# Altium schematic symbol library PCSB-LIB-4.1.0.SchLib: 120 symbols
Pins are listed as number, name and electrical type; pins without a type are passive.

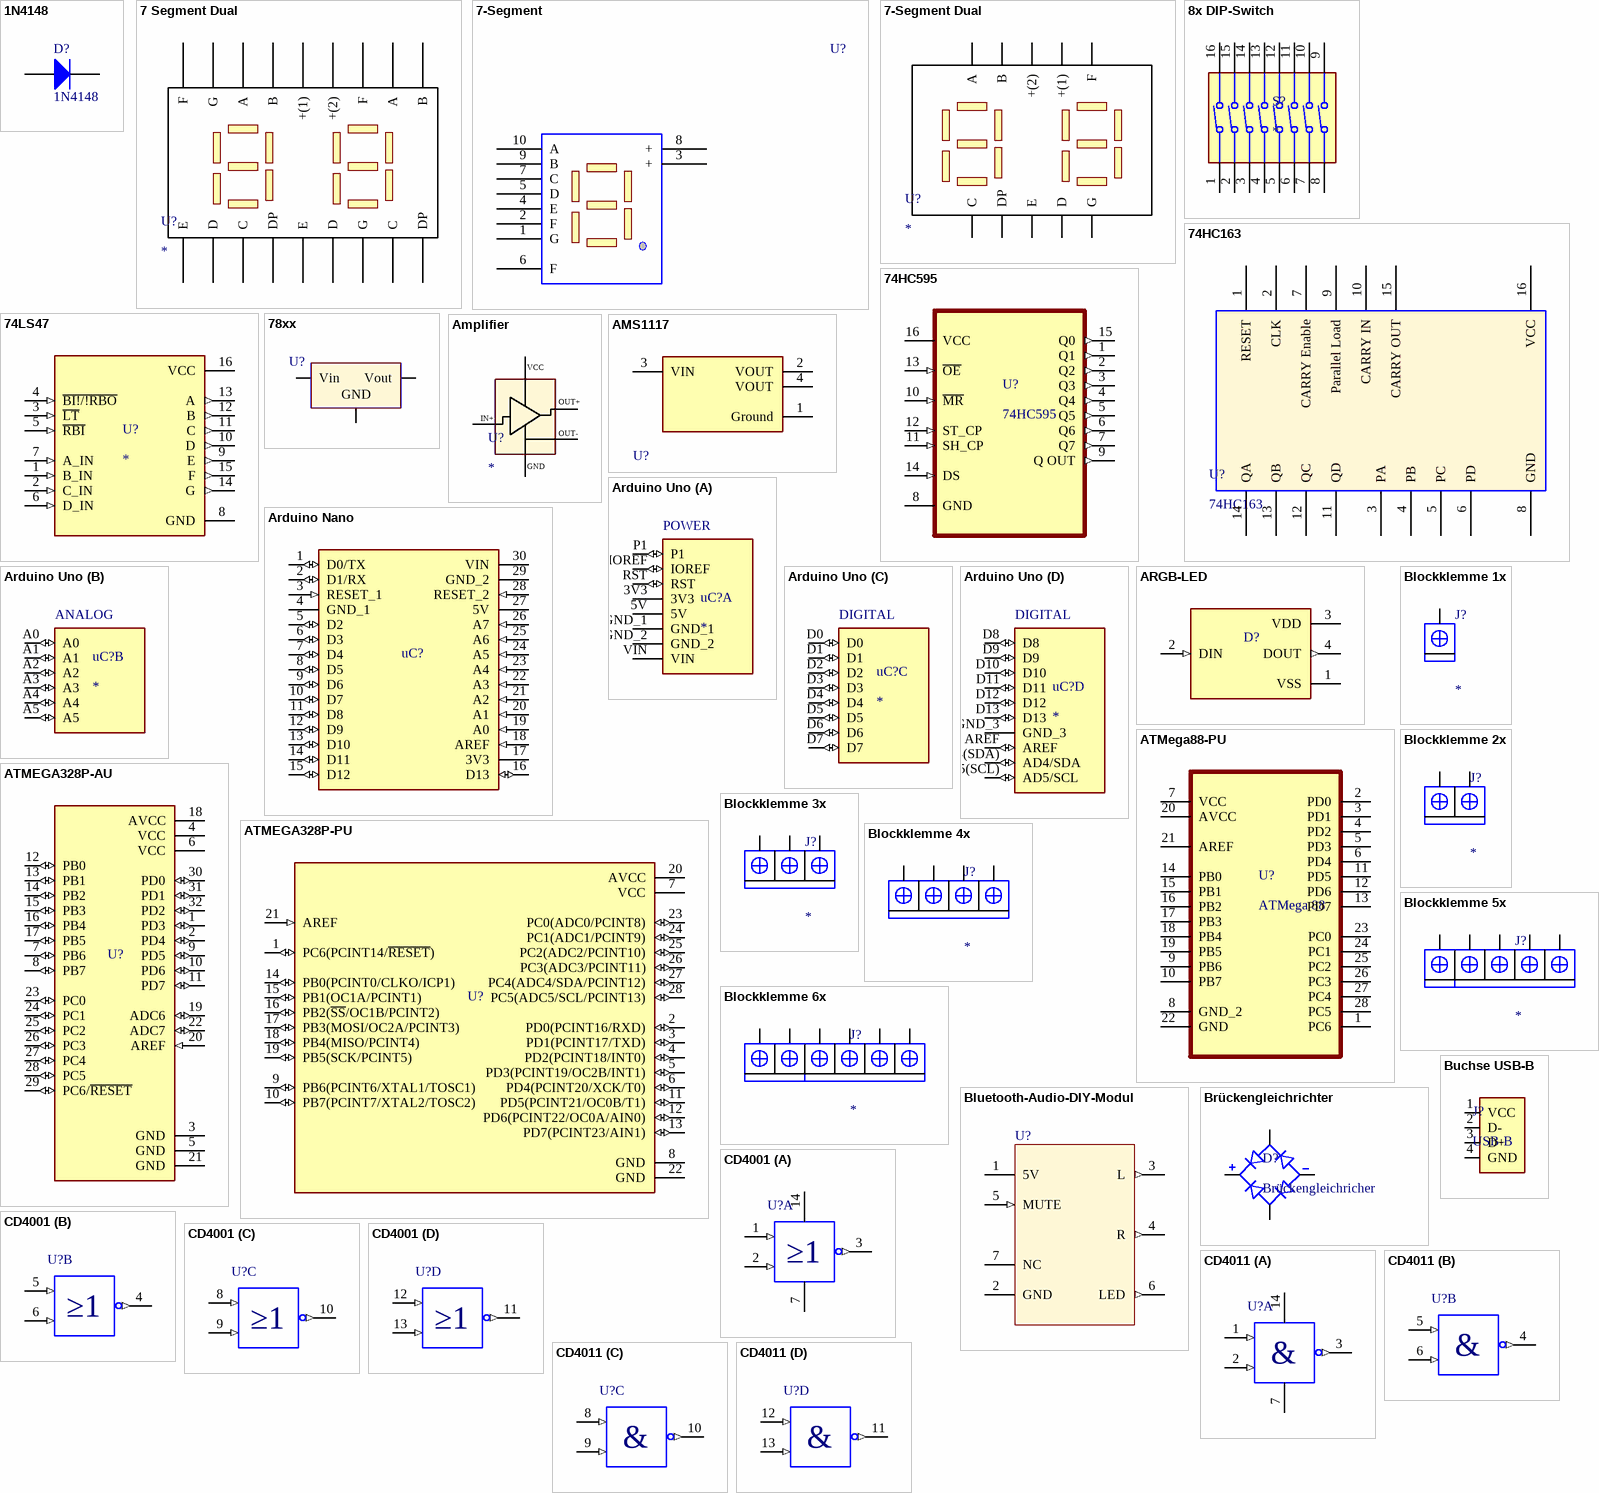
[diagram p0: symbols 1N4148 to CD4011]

## 1N4148
designator D?
Diode
footprint DIODE-0.4
pins: 1 A, 2 K

## 7 Segment Dual
designator U?
footprint 7 Segment Dual Klein
footprint 7 Segment Dual Groß
pins: 1 E, 2 D, 3 C, 4 DP, 5 E, 6 D, 7 G, 8 C, 9 DP, 10 B, 11 A, 12 F, 13 +(2), 14 +(1), 15 B, 16 A, 17 G, 18 F

## 7-Segment
designator U?  (value not drawn)
7-Segment Display
footprint 7-Segment
pins: 1 G, 2 F, 3 +, 4 E, 5 D, 6 F, 7 C, 8 +, 9 B, 10 A

## 7-Segment Dual
designator U?
footprint 7 Seg Einfach
pins: 1 C, 2 DP, 3 E, 4 D, 5 G, 6 F, 7 +(1), 8 +(2), 9 B, 10 A

## 8x DIP-Switch
designator S?
MP: 418117170908; MF: WÃ¼rth Elektronik
footprint DIP 2x8
pins: 1, 2, 3, 4, 5, 6, 7, 8, 9, 10, 11, 12, 13, 14, 15, 16

## 74HC163
designator U?
Counter-IC; Mfr_Name: Texas Instruments
footprint DIP-16
pins: 1 RESET, 2 CLK, 3 PA, 4 PB, 5 PC, 6 PD, 7 CARRY Enable, 8 GND, 9 Parallel Load, 10 CARRY IN, 11 QD, 12 QC, 13 QB, 14 QA, 15 CARRY OUT, 16 VCC

## 74HC595
designator U?
Schieberegister; MP: 74HC595PW/AUJ; MF: NXP Semiconductors
footprint SOP-16
footprint DIP-16
footprint SO-16
pins: 1 Q1 (out), 2 Q2 (out), 3 Q3 (out), 4 Q4 (out), 5 Q5 (out), 6 Q6 (out), 7 Q7 (out), 8 GND, 9 Q OUT (out), 10 ~{MR} (in), 11 SH_CP (in), 12 ST_CP (in), 13 ~{OE} (in), 14 DS (in), 15 Q0 (out), 16 VCC (power)

## 74LS47
designator U?
BCD-to-Seven-Segment Decoders/Drivers 16-PDIP 0 to 70; MP: SN74LS47N; MF: Texas Instruments
footprint DIP-16
footprint SO-16
pins: 1 B_IN (in), 2 C_IN (in), 3 ~{LT} (in), 4 ~{BI!/!RBO} (in), 5 ~{RBI} (in), 6 D_IN (in), 7 A_IN (in), 8 GND (power), 9 E (out), 10 D (out), 11 C (out), 12 B (out), 13 A (out), 14 G (out), 15 F (out), 16 VCC (power)

## 78xx
designator U?  (value not drawn)
Spannungswander
footprint TO-92/BCE
footprint TO-220H
footprint TO-220V
pins: 1 Vin, 2 Vout, 3 GND

## Amplifier
designator U?
footprint Verstärker 5V
pins: 0, 1, 2, 3, 4

## AMS1117
designator U?
Spannungswandler; Manufacturer Part Number: AMS1117-3.3; Manufacturer: Advanced Monolithic Systems; Dropout Voltage: 1.1V; Output Type: Fixed; Nominal Supply Current: 5mA; Output Current: 1A; Output Voltage: 3.3V; Max Power Dissipation: 1.2W; Max Supply Voltage: 15V; Number Of Outputs: 1; Standoff Height: 0.64mm; Max Junction Temp: +125°C
footprint AMS1117_1
footprint AMS1117_2
footprint AMS1117_3
pins: 1 Ground (power), 2 VOUT, 3 VIN (power), 4 VOUT

## Arduino Nano
designator uC?  (value not drawn)
Microcontroller; MP: A000005
footprint Arduino-Nano
pins: 1 D0/TX (io), 2 D1/RX (io), 3 RESET_1 (in), 4 GND_1 (power), 5 D2 (io), 6 D3 (io), 7 D4 (io), 8 D5 (io), 9 D6 (io), 10 D7 (io), 11 D8 (io), 12 D9 (io), 13 D10 (io), 14 D11 (io), 15 D12 (io), 16 D13 (io), 17 3V3 (power), 18 AREF (in), 19 A0 (in), 20 A1 (in), 21 A2 (in), 22 A3 (in), 23 A4 (in), 24 A5 (in), 25 A6 (in), 26 A7 (in), 27 5V (power), 28 RESET_2 (in), 29 GND_2 (power), 30 VIN (power)

## Arduino Uno
designator uC?
MP: A000066; MF: Arduino
footprint Arduino Uno
part A pins: 3V3 (power), 5V (power), GND_1 (power), GND_2 (power), IOREF (io), P1 (io), RST (io), VIN (power)
part B pins: A0 (io), A1 (io), A2 (io), A3 (io), A4 (io), A5 (io)
part C pins: D0 (io), D1 (io), D2 (io), D3 (io), D4 (io), D5 (io), D6 (io), D7 (io)
part D pins: A4(SDA) AD4/SDA (io), A5(SCL) AD5/SCL (io), AREF (io), D8 (io), D9 (io), D10 (io), D11 (io), D12 (io), D13 (io), GND_3 (power)

## ARGB-LED
designator D?  (value not drawn)
Addressable LED; MP: 1655
footprint LED_ARGB
pins: 1 VSS (power), 2 DIN (in), 3 VDD (power), 4 DOUT (out)

## ATMega88-PU
designator U?, comment ATMega 88
8-bit Microcontroller with In-System Programmable Flash; MP: ATMEGA88-20PU
footprint DIP-28
pins: 1 PC6, 2 PD0, 3 PD1, 4 PD2, 5 PD3, 6 PD4, 7 VCC, 8 GND_2, 9 PB6, 10 PB7, 11 PD5, 12 PD6, 13 PD7, 14 PB0, 15 PB1, 16 PB2, 17 PB3, 18 PB4, 19 PB5, 20 AVCC, 21 AREF, 22 GND, 23 PC0, 24 PC1, 25 PC2, 26 PC3, 27 PC4, 28 PC5

## ATMEGA328P-AU
designator U?, comment ATMega 328(p)  (value not drawn)
MF: Microchip Technology; MP: ATMEGA328P-AU
footprint ATMEGA328P
pins: 1 PD3 (io), 2 PD4 (io), 3 GND (power), 4 VCC (power), 5 GND (power), 6 VCC (power), 7 PB6 (io), 8 PB7 (io), 9 PD5 (io), 10 PD6 (io), 11 PD7 (io), 12 PB0 (io), 13 PB1 (io), 14 PB2 (io), 15 PB3 (io), 16 PB4 (io), 17 PB5 (io), 18 AVCC (power), 19 ADC6 (io), 20 AREF (in), 21 GND (power), 22 ADC7 (io), 23 PC0 (io), 24 PC1 (io), 25 PC2 (io), 26 PC3 (io), 27 PC4 (io), 28 PC5 (io), 29 PC6/~{RESET} (io), 30 PD0 (io), 31 PD1 (io), 32 PD2 (io)

## ATMEGA328P-PU
designator U?  (value not drawn)
Microcontroller; MF: Microchip Technology; MP: ATMEGA328-PU
footprint DIP-28
pins: 1 PC6(PCINT14/~{RESET}) (io), 2 PD0(PCINT16/RXD) (io), 3 PD1(PCINT17/TXD) (io), 4 PD2(PCINT18/INT0) (io), 5 PD3(PCINT19/OC2B/INT1) (io), 6 PD4(PCINT20/XCK/T0) (io), 7 VCC (power), 8 GND (power), 9 PB6(PCINT6/XTAL1/TOSC1) (io), 10 PB7(PCINT7/XTAL2/TOSC2) (io), 11 PD5(PCINT21/OC0B/T1) (io), 12 PD6(PCINT22/OC0A/AIN0) (io), 13 PD7(PCINT23/AIN1) (io), 14 PB0(PCINT0/CLKO/ICP1) (io), 15 PB1(OC1A/PCINT1) (io), 16 PB2(~{SS}/OC1B/PCINT2) (io), 17 PB3(MOSI/OC2A/PCINT3) (io), 18 PB4(MISO/PCINT4) (io), 19 PB5(SCK/PCINT5) (io), 20 AVCC (power), 21 AREF (in), 22 GND (power), 23 PC0(ADC0/PCINT8) (io), 24 PC1(ADC1/PCINT9) (io), 25 PC2(ADC2/PCINT10) (io), 26 PC3(ADC3/PCINT11) (io), 27 PC4(ADC4/SDA/PCINT12) (io), 28 PC5(ADC5/SCL/PCINT13) (io)

## Blockklemme 1x
designator J?
Stecker
footprint Blockklemme 1x
pins: 1

## Blockklemme 2x
designator J?
Stecker
footprint Blockklemme 2x
pins: 1, 2

## Blockklemme 3x
designator J?
Stecker
footprint Blockklemme 3x
pins: 1, 2, 3 2

## Blockklemme 4x
designator J?
Stecker
footprint Blockklemme 4x
pins: 1, 2, 3 2, 4 2

## Blockklemme 5x
designator J?
Stecker
footprint Blockklemme 5x
pins: 1, 2, 3 2, 4 2, 5 2

## Blockklemme 6x
designator J?
Stecker
footprint Blockklemme 6x
pins: 1, 2, 3 2, 4 2, 5 2, 6 2

## Bluetooth-Audio-DIY-Modul
designator U?  (value not drawn)
Bluetooth Modul
footprint Bluetooth Audio SIP7
pins: 1 5V (power), 2 GND (power), 3 L (out), 4 R (out), 5 MUTE (in), 6 LED (out), 7 NC

## Brückengleichrichter
designator D?, comment Brückengleichricher
MF: NTE Electronics, Inc; MP: NTE53010
footprint FBR_Big
footprint FBR-little
pins: 1 POS, 2 AC1, 3 AC2, 4 NEG

## Buchse USB-B
designator J?, comment USB-B
MF: On Shore; MP: USB-B1HSB6
footprint USB-B
pins: 1 VCC (power), 2 D- (io), 3 D+ (io), 4 GND (power)

## CD4001
designator U?  (value not drawn)
NOR Gatter; PartNumber: LM358AN; Manufacturer: National Semiconductor; PackageTopMarking: NSUZXYTTE#*LM*358AN; PowerWise: N; CompType: Amplifiers
footprint DIP-14
footprint SO-14
part A pins: 1 A (in), 2 B (in), 3 OUTAB (out), 7 GND (power), 14 V+ (power)
part B pins: 4 OUTCD (out), 5 C (in), 6 D (in)
part C pins: 8 E (in), 9 F (in), 10 OUTEF (out)
part D pins: 11 OUTGH (out), 12 G (in), 13 H (in)

## CD4011
designator U?  (value not drawn)
NAND Gatter; PartNumber: LM358AN; Manufacturer: National Semiconductor; PackageTopMarking: NSUZXYTTE#*LM*358AN; PowerWise: N; CompType: Amplifiers
footprint DIP-14
footprint SO-14
part A pins: 1 A (in), 2 B (in), 3 OUTAB (out), 7 GND (power), 14 V+ (power)
part B pins: 4 OUTCD (out), 5 C (in), 6 D (in)
part C pins: 8 E (in), 9 F (in), 10 OUTEF (out)
part D pins: 11 OUTGH (out), 12 G (in), 13 H (in)

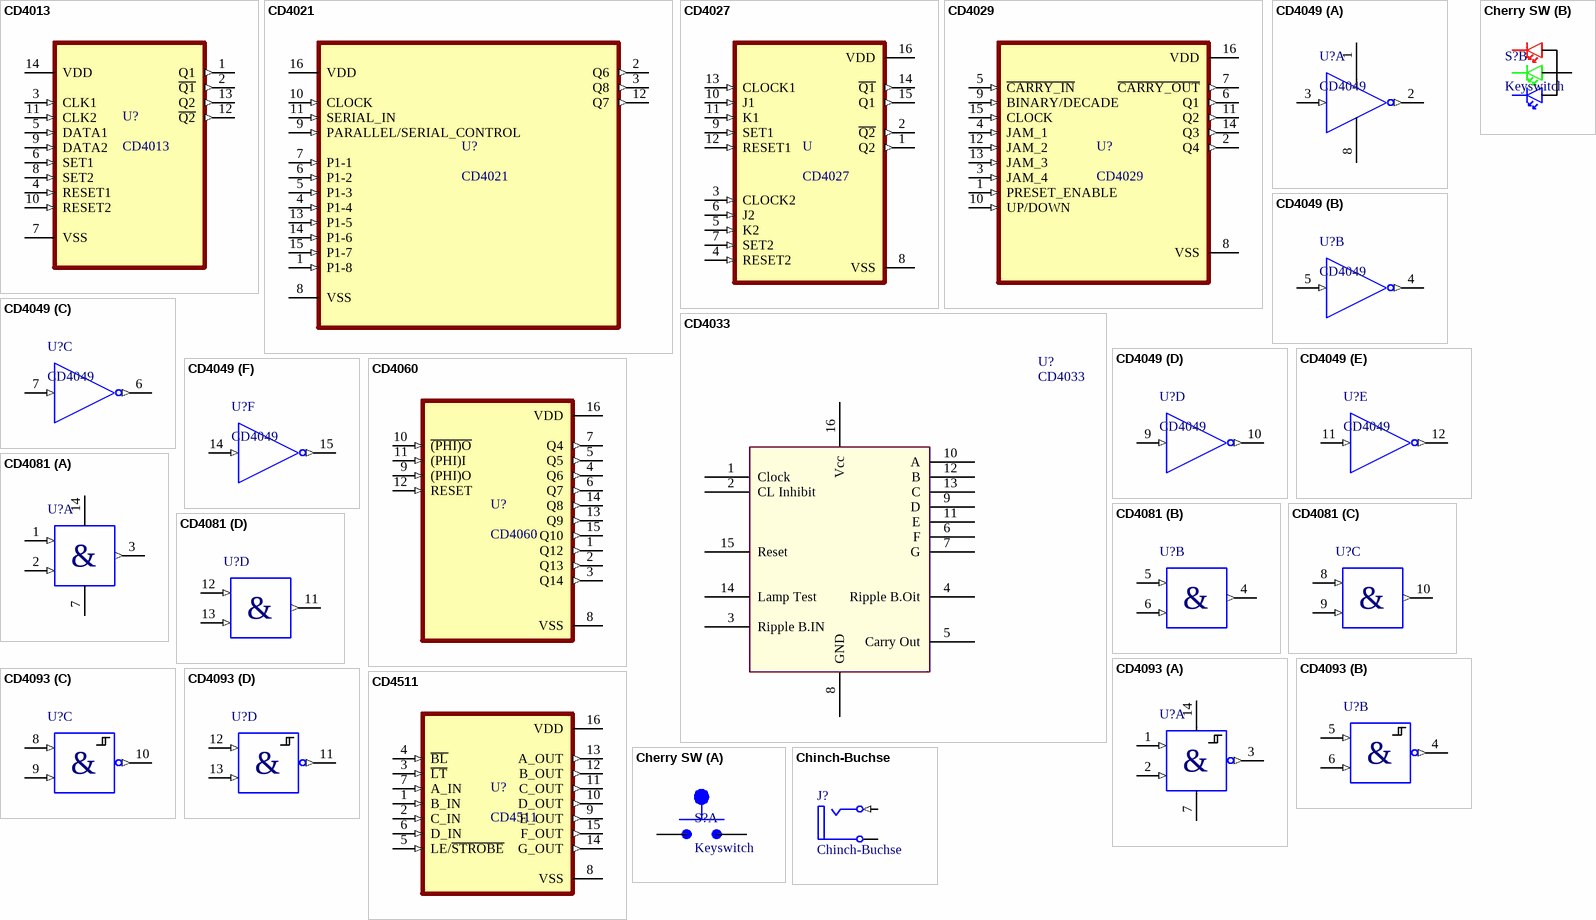
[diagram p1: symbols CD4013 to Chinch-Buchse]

## CD4013
designator U?
D-FlipFlop; MP: CD4013BCN; MF: ON Semiconductor
footprint DIP-14
footprint SO-14
pins: 1 Q1 (out), 2 ~{Q1} (out), 3 CLK1 (in), 4 RESET1 (in), 5 DATA1 (in), 6 SET1 (in), 7 VSS (power), 8 SET2 (in), 9 DATA2 (in), 10 RESET2 (in), 11 CLK2 (in), 12 ~{Q2} (out), 13 Q2 (out), 14 VDD (power)

## CD4021
designator U?
Schieberegister; MF: Texas Instruments; MP: CD4021BEE4
footprint DIP-16
pins: 1 P1-8 (in), 2 Q6 (out), 3 Q8 (out), 4 P1-4 (in), 5 P1-3 (in), 6 P1-2 (in), 7 P1-1 (in), 8 VSS, 9 PARALLEL/SERIAL_CONTROL (in), 10 CLOCK (in), 11 SERIAL_IN (in), 12 Q7 (out), 13 P1-5 (in), 14 P1-6 (in), 15 P1-7 (in), 16 VDD (power)

## CD4027
designator U
JK-FlipFlop; MP: CD4027BE; MF: Texas Instruments
footprint DIP-16
pins: 1 Q2 (out), 2 ~{Q2} (out), 3 CLOCK2 (in), 4 RESET2 (in), 5 K2 (in), 6 J2 (in), 7 SET2 (in), 8 VSS (power), 9 SET1 (in), 10 J1 (in), 11 K1 (in), 12 RESET1 (in), 13 CLOCK1 (in), 14 ~{Q1} (out), 15 Q1 (out), 16 VDD (power)

## CD4029
designator U?
UP/Down Counter; MP: CD4029BE; MF: Texas Instruments
footprint DIP-16
pins: 1 PRESET_ENABLE (in), 2 Q4 (out), 3 JAM_4 (in), 4 JAM_1 (in), 5 ~{CARRY_IN} (in), 6 Q1 (out), 7 ~{CARRY_OUT} (out), 8 VSS (power), 9 BINARY/DECADE (in), 10 UP/DOWN (in), 11 Q2 (out), 12 JAM_2 (in), 13 JAM_3 (in), 14 Q3 (out), 15 CLOCK (in), 16 VDD (power)

## CD4033
designator U?
Counter/Divider
footprint DIP-16
footprint SO-16
pins: 1 Clock, 2 CL Inhibit, 3 Ripple B.IN, 4 Ripple B.Oit, 5 Carry Out, 6 F, 7 G, 8 GND, 9 D, 10 A, 11 E, 12 B, 13 C, 14 Lamp Test, 15 Reset, 16 Vcc

## CD4049
designator U?
Hex Inverter; PartNumber: LM358AN; Manufacturer: National Semiconductor; PackageTopMarking: NSUZXYTTE#*LM*358AN; PowerWise: N; CompType: Amplifiers
footprint DIP-16
part A pins: 1 V+ (power), 2 OUTAB (out), 3 B (in), 8 GND (power)
part B pins: 4 OUTAB (out), 5 B (in)
part C pins: 6 OUTAB (out), 7 B (in)
part D pins: 9 B (in), 10 OUTAB (out)
part E pins: 11 B (in), 12 OUTAB (out)
part F pins: 14 B (in), 15 OUTAB (out)

## CD4060
designator U?
14 Stage Counter; MP: CD4060BE; MF: Texas Instruments
footprint DIP-16
pins: 1 Q12 (out), 2 Q13 (out), 3 Q14 (out), 4 Q6 (out), 5 Q5 (out), 6 Q7 (out), 7 Q4 (out), 8 VSS (power), 9 (PHI)O (in), 10 ~{(PHI)O} (in), 11 (PHI)I (in), 12 RESET (in), 13 Q9 (out), 14 Q8 (out), 15 Q10 (out), 16 VDD (power)

## CD4081
designator U?  (value not drawn)
AND Gatter; PartNumber: LM358AN; Manufacturer: National Semiconductor; PackageTopMarking: NSUZXYTTE#*LM*358AN; PowerWise: N; CompType: Amplifiers
footprint DIP-14
footprint SO-14
part A pins: 1 A (in), 2 B (in), 3 OUTAB (out), 7 GND (power), 14 V+ (power)
part B pins: 4 OUTCD (out), 5 C (in), 6 D (in)
part C pins: 8 E (in), 9 F (in), 10 OUTEF (out)
part D pins: 11 OUTGH (out), 12 G (in), 13 H (in)

## CD4093
designator U?  (value not drawn)
Schmitttrigger NAND Gatter; PartNumber: LM358AN; Manufacturer: National Semiconductor; PackageTopMarking: NSUZXYTTE#*LM*358AN; PowerWise: N; CompType: Amplifiers
footprint DIP-14
footprint SO-14
part A pins: 1 A (in), 2 B (in), 3 OUTAB (out), 7 GND (power), 14 V+ (power)
part B pins: 4 OUTCD (out), 5 C (in), 6 D (in)
part C pins: 8 E (in), 9 F (in), 10 OUTEF (out)
part D pins: 11 OUTGH (out), 12 G (in), 13 H (in)

## CD4511
designator U?
BCD; MP: CD4511BE
footprint DIP-16
pins: 1 B_IN (in), 2 C_IN (in), 3 ~{LT} (in), 4 ~{BL} (in), 5 LE/~{STROBE} (in), 6 D_IN (in), 7 A_IN (in), 8 VSS (power), 9 E_OUT (out), 10 D_OUT (out), 11 C_OUT (out), 12 B_OUT (out), 13 A_OUT (out), 14 G_OUT (out), 15 F_OUT (out), 16 VDD (power)

## Cherry SW
designator S?, comment Keyswitch
Switch Key N.O. SPST 0.01A 12VAC 12VDC 0.5N PC Pins 20000000Cycles Thru-Hole; MP: COM-13834
footprint Cherry MX
footprint Cherry MX - LED
part A pins: 1, 2
part B pins: 3, 4, 5, 6

## Chinch-Buchse
designator J?
PackageDocument: 2003; PCB_Layout: Complies with manufacturer's recommendation.; DrillAndSlotSize: Corresponds to nominal value.; Lieferant: RS; Bestellnummer: 909-2235; Preis /Stk: 0,790
footprint CHINCH (RCA-Buchse bestellbar bei RS  Nr. 913-1021)
pins: 1 T (in) "Tip", 5 S (power) "Sleeve (Ground)"

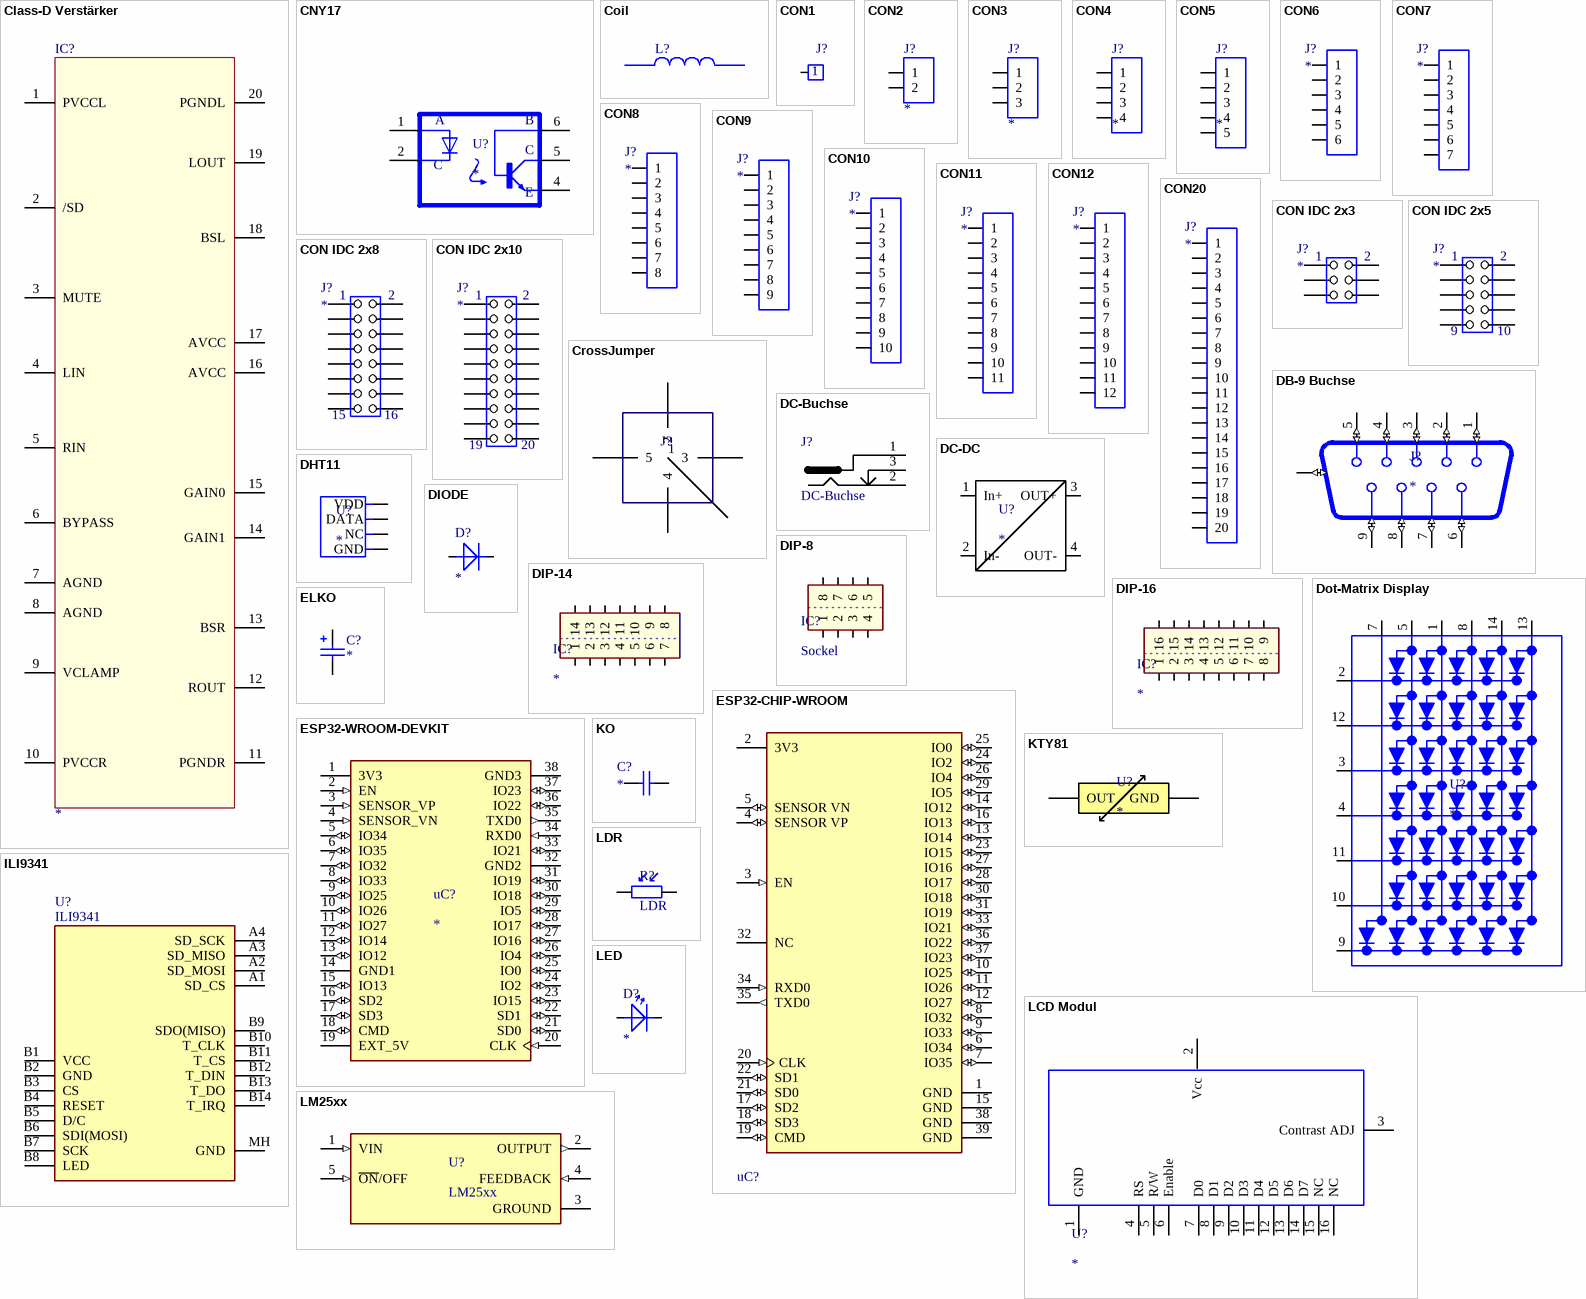
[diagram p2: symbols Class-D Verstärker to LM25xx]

## Class-D Verstärker
designator IC?
Class-D; Value: TPA3125; Lieferant: RS; Bestellnummer: 121-9381; Preis /Stk: 1,977
footprint DIP-20
pins: 1 PVCCL, 2 /SD, 3 MUTE, 4 LIN, 5 RIN, 6 BYPASS, 7 AGND, 8 AGND, 9 VCLAMP, 10 PVCCR, 11 PGNDR, 12 ROUT, 13 BSR, 14 GAIN1, 15 GAIN0, 16 AVCC, 17 AVCC, 18 BSL, 19 LOUT, 20 PGNDL

## CNY17
designator U?
Optoisolator Transistor Output 5000Vrms 1 Channel 6-DIP; MP: CNY17F-3; MF: Vishay Semiconductor
footprint DIP-6
pins: 1 A, 2 C, 4 E, 5 C`, 6

## Coil
designator L?, comment 80Ohm@100MHz  (value not drawn)
Spule; Lieferant: Pollin; Bestellnummer: 888-3033; Preis /Stk: 0,051
footprint Axial-0.4
footprint Coil - 5.08 x 8
footprint 1808C (Chip Capacitor, 2-Leads, Body 4,5x2,0mm, IPC Medium Density)
footprint NPIS42LS (SMD-Footprint für Spulen)
pins: 1, 2

## CON1
designator J?  (value not drawn)
Stecker
footprint SIP-1
pins: 1

## CON2
designator J?
Stecker
footprint KL-2
footprint SIP-2
pins: 1, 2

## CON3
designator J?
Stecker
footprint Sip-3
footprint KL-3
pins: 1, 2, 3

## CON4
designator J?
Stecker
footprint Sip-4
pins: 1, 2, 3, 4

## CON5
designator J?
Stecker
footprint SIP-5
pins: 1, 2, 3, 4, 5

## CON6
designator J?
Stecker
footprint SIP-6
pins: 1, 2, 3, 4, 5, 6

## CON7
designator J?
Stecker
footprint SIP-7
pins: 1, 2, 3, 4, 5, 6, 7

## CON8
designator J?
Stecker
footprint SIP-8
pins: 1, 2, 3, 4, 5, 6, 7, 8

## CON9
designator J?
Stecker
footprint SIP-9
footprint DB9SL
pins: 1, 2, 3, 4, 5, 6, 7, 8, 9

## CON10
designator J?
Stecker
footprint SIP-10
pins: 1, 2, 3, 4, 5, 6, 7, 8, 9, 10

## CON11
designator J?
Stecker
footprint SIP-11
pins: 1, 2, 3, 4, 5, 6, 7, 8, 9, 10, 11

## CON12
designator J?
Stecker
footprint SIP-12
pins: 1, 2, 3, 4, 5, 6, 7, 8, 9, 10, 11, 12

## CON20
designator J?
Stecker
footprint SIP-20
pins: 1, 2, 3, 4, 5, 6, 7, 8, 9, 10, 11, 12, 13, 14, 15, 16, 17, 18, 19, 20

## CON IDC 2x3
designator J?
Stecker
footprint PFOSTEN_2x3
pins: 1, 2, 3, 4, 5, 6

## CON IDC 2x5
designator J?
Stecker
footprint PFOSTEN_2x5H
footprint PFOSTEN_2x5V
pins: 1, 2, 3, 4, 5, 6, 7, 8, 9, 10

## CON IDC 2x8
designator J?
Stecker
footprint PFOSTEN_2x8
pins: 1, 2, 3, 4, 5, 6, 7, 8, 9, 10, 11, 12, 13, 14, 15, 16

## CON IDC 2x10
designator J?
Stecker
footprint PFOSTEN_2x10
pins: 1, 2, 3, 4, 5, 6, 7, 8, 9, 10, 11, 12, 13, 14, 15, 16, 17, 18, 19, 20

## CrossJumper
designator J?  (value not drawn)
footprint CrossJumper
pins: 1, 2, 3, 4, 5

## DB-9 Buchse
designator J?
MF: Wurth Electronics; MP: 618009231121
footprint Serial
pins: 1 (io), 2 (io), 3 (io), 4 (io), 5 (io), 6 (io), 7 (io), 8 (io), 9 (io), SHELL SHIELD (io), SHELL1 SHIELD (io)

## DC-Buchse
designator J?
Lieferant: RS; Bestellnummer: 448-382; Preis /Stk: 0,267
footprint CJ-25 (DC-Buchse 2.1mm Bestellbar bei RS Nr. 448-382)
pins: 1, 2, 3

## DC-DC
designator U?
DC-DC Wandler
footprint dcdc
pins: 1 In+, 2 In-, 3 OUT+, 4 OUT-

## DHT11
designator U?
Temparatur Sensor; MP: DHT11; MF: Panasonic Industrial Automation Sales
footprint SNR4-2.54-15.5X12.0X5.5MM
pins: 1 VDD (power), 2 DATA (power), 3 NC, 4 GND (power)

## DIODE
designator D?
Diode
footprint Diode-0.4
footprint Diode-0.5
footprint DIODE-0.6
footprint 0603 - DIO
footprint 0805 - DIO
pins: 1 A, 2 K

## DIP-8
designator IC?, comment Sockel
footprint DIP-8
footprint SO-8
pins: 1, 2, 3, 4, 5, 6, 7, 8

## DIP-14
designator IC?
footprint DIP-14
footprint SO-14
pins: 1, 2, 3, 4, 5, 6, 7, 8, 9, 10, 11, 12, 13, 14

## DIP-16
designator IC?
footprint DIP-16
footprint SO-16
pins: 1, 2, 3, 4, 5, 6, 7, 8, 9, 10, 11, 12, 13, 14, 15, 16

## Dot-Matrix Display
designator U?
Dot Matrix Display Module 5 x 7 Common Cathode Row, Common Anode Column Green 2.1V 0.39 L x 0.73 W x 0.14 H (9.80mm x 18.50mm x 3.50mm); MF: Lite-On Inc.; MP: LTP-305G
footprint DOTMatrixDisplay
pins: 1 ANODE_COLUMN_2, 2 CATHODE_ROW_1, 3 CATHODE_ROW_3, 4 CATHODE_ROW_4, 5 ANODE_COLUMN_1, 7 ANODE_DECIMAL_POINT, 8 ANODE_COLUMN_3, 9 CATHODE_ROW_7, 10 CATHODE_ROW_6, 11 CATHODE_ROW_5, 12 CATHODE_ROW_2, 13 ANODE_COLUMN_5, 14 ANODE_COLUMN_4

## ELKO
designator C?
Elko
footprint RB-.1/.2
footprint RB-.1/.3
footprint RB-.2/.4
footprint RB-.3/.6
footprint CAP_SMD_Radial_Typ-G
footprint CAP_SMD_RADIAL_Typ-F
footprint CAP_SMD_RADIAL_TYP-D
pins: 1, 2

## ESP32-CHIP-WROOM
designator uC?
Microcontroller; Manufacturer: Espressif Systems; Manufacturer Part Number: ESP32-WROOM-32D; Max Supply Voltage: 3.6V; Nominal Supply Current: 500mA; Max Frequency: 2484MHz; Number Of Adc Channels: 16; Number Of Gpio: 32; Interface: I2C,SPI,UART,Ethernet,I2S,Other; Data Rate: 150Mbits/s; Min Supply Voltage: 3V; Bandwidth: 72MHz; Sensitivity: -98dBm
footprint ESP32-DEV
pins: 1 GND (power), 2 3V3 (power), 3 EN (in), 4 SENSOR VP (io), 5 SENSOR VN (io), 6 IO34 (io), 7 IO35 (io), 8 IO32 (io), 9 IO33 (io), 10 IO25 (io), 11 IO26 (io), 12 IO27 (io), 13 IO14 (io), 14 IO12 (io), 15 GND (power), 16 IO13 (io), 17 SD2 (io), 18 SD3 (io), 19 CMD (io), 20 CLK (in), 21 SD0 (io), 22 SD1 (io), 23 IO15 (io), 24 IO2 (io), 25 IO0 (io), 26 IO4 (io), 27 IO16 (io), 28 IO17 (io), 29 IO5 (io), 30 IO18 (io), 31 IO19 (io), 32 NC, 33 IO21 (io), 34 RXD0 (in), 35 TXD0 (out), 36 IO22 (io), 37 IO23 (io), 38 GND (power), 39 GND (power)

## ESP32-WROOM-DEVKIT
designator uC?
MP: ESP32-DEVKITC; MF: Espressif Systems
footprint ESP32-WROOM
pins: 1 3V3 (power), 2 EN (in), 3 SENSOR_VP (in), 4 SENSOR_VN (in), 5 IO34 (io), 6 IO35 (io), 7 IO32 (io), 8 IO33 (io), 9 IO25 (io), 10 IO26 (io), 11 IO27 (io), 12 IO14 (io), 13 IO12 (io), 14 GND1 (power), 15 IO13 (io), 16 SD2 (io), 17 SD3 (io), 18 CMD (io), 19 EXT_5V (power), 20 CLK (in), 21 SD0 (io), 22 SD1 (io), 23 IO15 (io), 24 IO2 (io), 25 IO0 (io), 26 IO4 (io), 27 IO16 (io), 28 IO17 (io), 29 IO5 (io), 30 IO18 (io), 31 IO19 (io), 32 GND2 (power), 33 IO21 (io), 34 RXD0 (in), 35 TXD0 (out), 36 IO22 (io), 37 IO23 (io), 38 GND3 (power)

## ILI9341
designator U?
Color 320x240 TFT Touchscreen, ILI9341 Controller Chip; Manufacturer_Name: PJRC; Geometry.Height: 7mm
footprint ILI9341
pins: A1 SD_CS, A2 SD_MOSI, A3 SD_MISO, A4 SD_SCK, B1 VCC, B2 GND, B3 CS, B4 RESET, B5 D/C, B6 SDI(MOSI), B7 SCK, B8 LED, B9 SDO(MISO), B10 T_CLK, B11 T_CS, B12 T_DIN, B13 T_DO, B14 T_IRQ, MH GND

## KO
designator C?
Kondensator
footprint rad-7.2/2.5/5
footprint RAD-7.2/3.5/5
footprint 0603
footprint 0805
footprint 1206
footprint KO-600mil
pins: 1, 2

## KTY81
designator U?
PTC Thermistor 2 kOhms TO-226-2, TO-92-2 (TO-226AC); MP: KTY81; MF: NXP USA
footprint TO-92/2
pins: 1 OUT, 2 GND

## LCD Modul
designator U?
LCD
footprint WM-C1610M
pins: 1 GND, 2 Vcc, 3 Contrast ADJ, 4 RS, 5 R/W, 6 Enable, 7 D0, 8 D1, 9 D2, 10 D3, 11 D4, 12 D5, 13 D6, 14 D7, 15 NC, 16 NC

## LDR
designator R?
MP: NSL-19M51; MF: Advanced Photonix
footprint LDR
pins: 1, 2

## LED
designator D?
Diode
footprint LED-5
footprint LED-3
footprint 0603 - DIO
footprint 0805 - DIO
pins: 1 A, 2 K

## LM25xx
designator U?
Spanungswandler; MP: LM2576T-ADJ; MF: Texas Instruments
footprint TO220-5
footprint TO-220-5
pins: 1 VIN (in), 2 OUTPUT (out), 3 GROUND (power), 4 FEEDBACK (in), 5 ~{ON}/OFF (in)

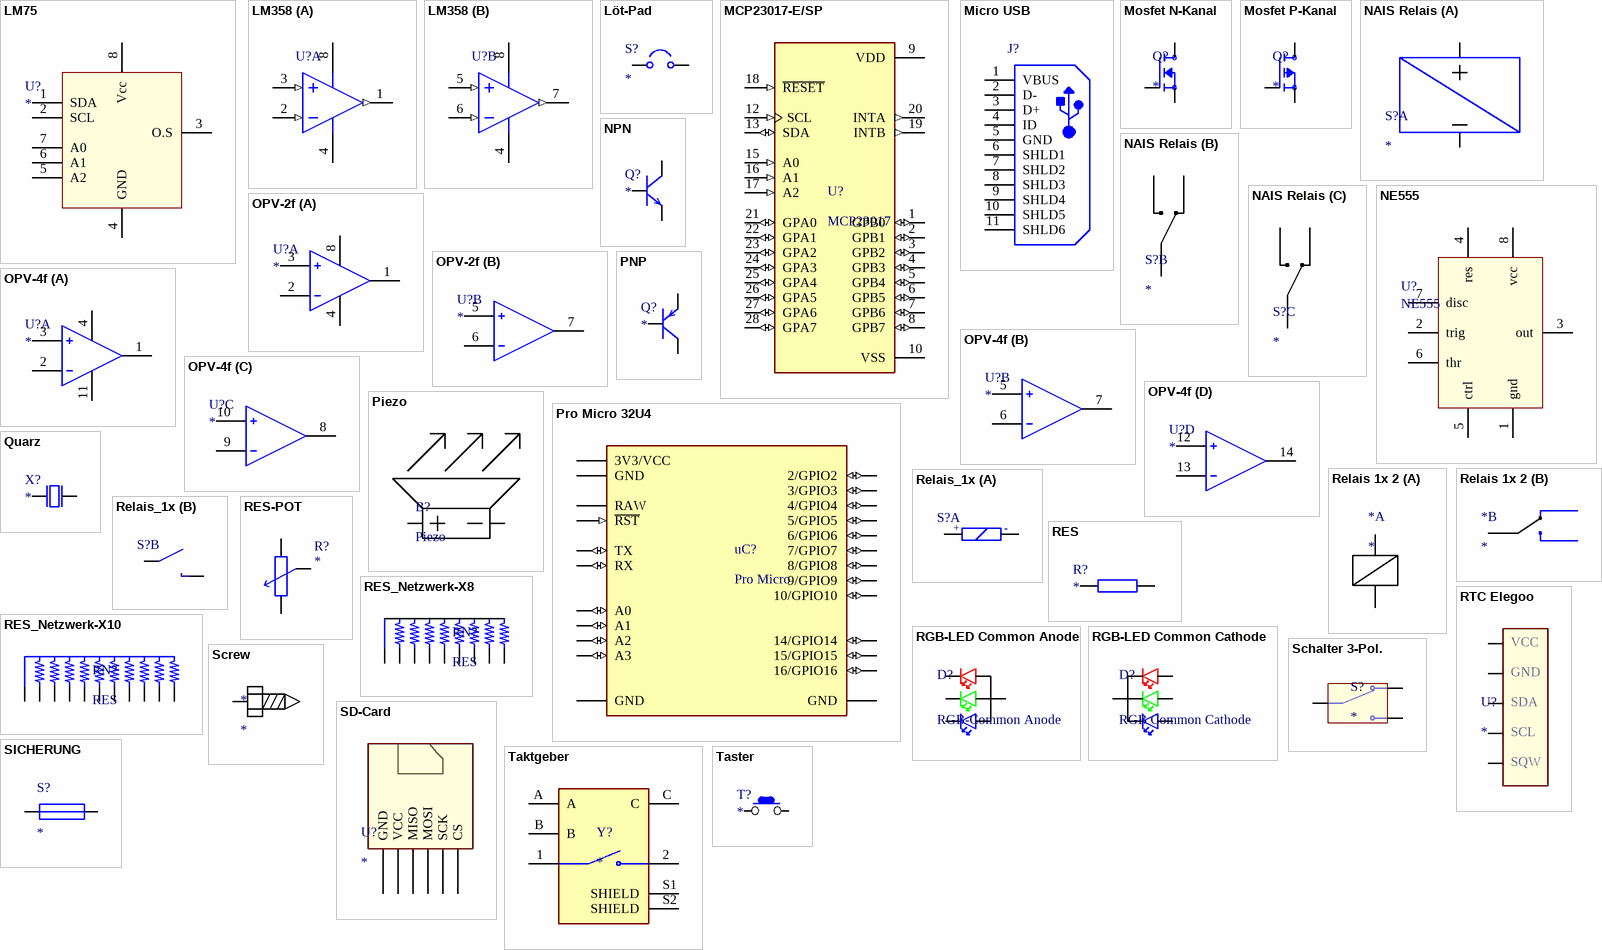
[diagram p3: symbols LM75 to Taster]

## LM75
designator U?
IC
footprint SO-8
pins: 1 SDA, 2 SCL, 3 O.S, 4 GND, 5 A2, 6 A1, 7 A0, 8 Vcc

## LM358
designator U?
Operationsverstärker; PartNumber: LM358AN; Manufacturer: National Semiconductor; PackageTopMarking: NSUZXYTTE#*LM*358AN; PowerWise: N; CompType: Amplifiers
footprint DIP-8
footprint SO-8
pins on every part: 4 GND (power), 8 V+ (power)
part A pins: 1 OUTA (out), 2 INA- (in), 3 INA+ (in)
part B pins: 5 INB+ (in), 6 INB- (in), 7 OUTB (out)

## Löt-Pad
designator S?
footprint SMD-Brigde NC
footprint SMD-Brigde NO
pins: 1 0, 2 1

## MCP23017-E/SP
designator U?, comment MCP23017
MF: Microchip; MP: MCP23017-E/SP
footprint DIP-28
pins: 1 GPB0 (io), 2 GPB1 (io), 3 GPB2 (io), 4 GPB3 (io), 5 GPB4 (io), 6 GPB5 (io), 7 GPB6 (io), 8 GPB7 (io), 9 VDD (power), 10 VSS (power), 12 SCL (in), 13 SDA (io), 15 A0 (in), 16 A1 (in), 17 A2 (in), 18 ~{RESET} (in), 19 INTB (out), 20 INTA (out), 21 GPA0 (io), 22 GPA1 (io), 23 GPA2 (io), 24 GPA3 (io), 25 GPA4 (io), 26 GPA5 (io), 27 GPA6 (io), 28 GPA7 (io)

## Micro USB
designator J?
Number of Ports: 1Port; Current Rating: 1.8A; Brand: Molex; Mounting Angle: Right; Gender: Female; Connector Type: MicroUSBTypeABreceptacle; Number of Contacts: 5Contact; Voltage Rating: 30VAC
footprint Micro-USB (USB, MICRO B, Body 7.491x4.695 mm, Pitch 0.65 mm)
pins: 1 VBUS, 2 D-, 3 D+, 4 ID, 5 GND, 6 SHLD1, 7 SHLD2, 8 SHLD3, 9 SHLD4, 10 SHLD5, 11 SHLD6

## Mosfet N-Kanal
designator Q?
FET; MP: IRFZ44NPBF; MF: Infineon
footprint MOSFET
footprint SOT-23-FET
pins: 1 G, 2 D, 3 S

## Mosfet P-Kanal
designator Q?
FET; MP: IRFZ44NPBF; MF: Infineon
footprint MOSFET
footprint SOT-23-FET
pins: 1 G, 2 D, 3 S

## NAIS Relais
designator S?
footprint NAIS-Relais
part A pins: 4, 5
part B pins: 1, 2, 3
part C pins: 6, 7, 8

## NE555
designator U?
Timer
footprint DIP-8
footprint SO-8
pins: 1 gnd, 2 trig, 3 out, 4 res, 5 ctrl, 6 thr, 7 disc, 8 vcc

## NPN
designator Q?
Transistor
footprint TO-92/EBC
footprint TO-220V
footprint TO-220H
footprint TO3
pins: 1 B, 2 E, 3 C

## OPV-2f
designator U?
IC
footprint DIP-8
footprint SO-8
part A pins: 1 out, 2 I, 3 NI, 4 Vee, 8 Vcc
part B pins: 5 NI, 6 I, 7 out

## OPV-4f
designator U?
IC
footprint DIP-14
footprint SO-14
part A pins: 1 out, 2 I, 3 NI, 4 Vcc, 11 Vee
part B pins: 5 NI, 6 I, 7 out
part C pins: 8 out, 9 I, 10 NI
part D pins: 12 NI, 13 I, 14 out

## Piezo
designator B?
footprint Piezo
pins: 1, 2

## PNP
designator Q?
Transistor
footprint TO-92/EBC
footprint TO-220V
footprint TO-220H
pins: 1 B, 2 E, 3 C

## Pro Micro 32U4
designator uC?, comment Pro Micro
MF: SparkFun Electronics; MP: DEV-18288
footprint Pro Micro 32U4
pins: J3_1 9/GPIO9 (io), J3_2 8/GPIO8 (io), J3_3 7/GPIO7 (io), J3_4 6/GPIO6 (io), J3_5 5/GPIO5 (io), J3_6 4/GPIO4 (io), J3_7 3/GPIO3 (io), J3_8 2/GPIO2 (io), J3_9 GND (power), J3_10 GND (power), J3_11 RX (io), J3_12 TX (io), J4_1 RAW (power), J4_2 GND (power), J4_3 ~{RST} (in), J4_4 3V3/VCC (power), J4_5 A3 (io), J4_6 A2 (io), J4_7 A1 (io), J4_8 A0 (io), J4_9 15/GPIO15 (io), J4_10 14/GPIO14 (io), J4_11 16/GPIO16 (io), J4_12 10/GPIO10 (io)

## Quarz
designator X?
Quarz
footprint Quarz
footprint XTAL SMD
pins: 1, 2

## Relais 1x 2
designator *
footprint Relais 1x 2
part A pins: 1 +, 2
part B pins: 3, 4 NO, 5

## Relais_1x
designator S?
Relais
footprint Relais (K?)
part A pins: 1 +, 2 -
part B pins: 3, 4

## RES
designator R?
Widerstand
footprint Axial-0.4
footprint Axial-0.7
footprint 0603
footprint 0805
footprint 1206
simulation model Model Name (Model Description)
footprint Res-V
pins: 1, 2

## RES-POT
designator R?
Potentiometer; Set Position: 0.5
footprint PT15
footprint TP-.2/.4
footprint ALPS_V
pins: 1, 2, 3

## RES_Netzwerk-X8
designator RN?, comment RES
MF: Bourns; MP: 4611X-101-103
footprint Res-Netzwerk-8
pins: 1, 2, 3, 4, 5, 6, 7, 8, 9

## RES_Netzwerk-X10
designator RN?, comment RES
MF: Bourns; MP: 4611X-101-103
footprint RES-Netzwerk-10
pins: 1, 2, 3, 4, 5, 6, 7, 8, 9, 10, 11

## RGB-LED Common Anode
designator D?, comment RGB-Common Anode
Diode
footprint RGBLED
pins: 1, 2, 3, 4

## RGB-LED Common Cathode
designator D?, comment RGB Common Cathode
Diode
footprint RGBLED
pins: 1, 2, 3, 4

## RTC Elegoo
designator U?
footprint Elegoo RTC
pins: 1, 2, 3, 4, 5

## Schalter 3-Pol.
designator S?
Toggle Switch; MP: 100SP1T1B4M2QE
footprint SW_100SP1T1B4M2QE
pins: 1, 2, 3

## Screw
designator *
footprint Schraube-M3 (Befestigungsschraube für Prints)
footprint Schraube-M3 PAD (Befestigungsschraube für Prints)
pins: 1 PAD

## SD-Card
designator U?
footprint SD-Card - H
footprint SD-Card - V
pins: 0 GND, 1 VCC, 2 MISO, 3 MOSI, 4 SCK, 5 CS

## SICHERUNG
designator S?
Sicherung; Text Field1: Strom
footprint SICHERUNG
pins: 1, 2

## Taktgeber
designator Y?
Rotary Encoder; MP: 482016514001; MF: WÃ¼rth Elektronik
footprint Rotary
pins: 1, 2, A, B, C, S1 SHIELD, S2 SHIELD

## Taster
designator T?
Taster
footprint Tast
footprint Taster 20mm
footprint Taster Gross
footprint Taster Kombi
pins: 1, 2

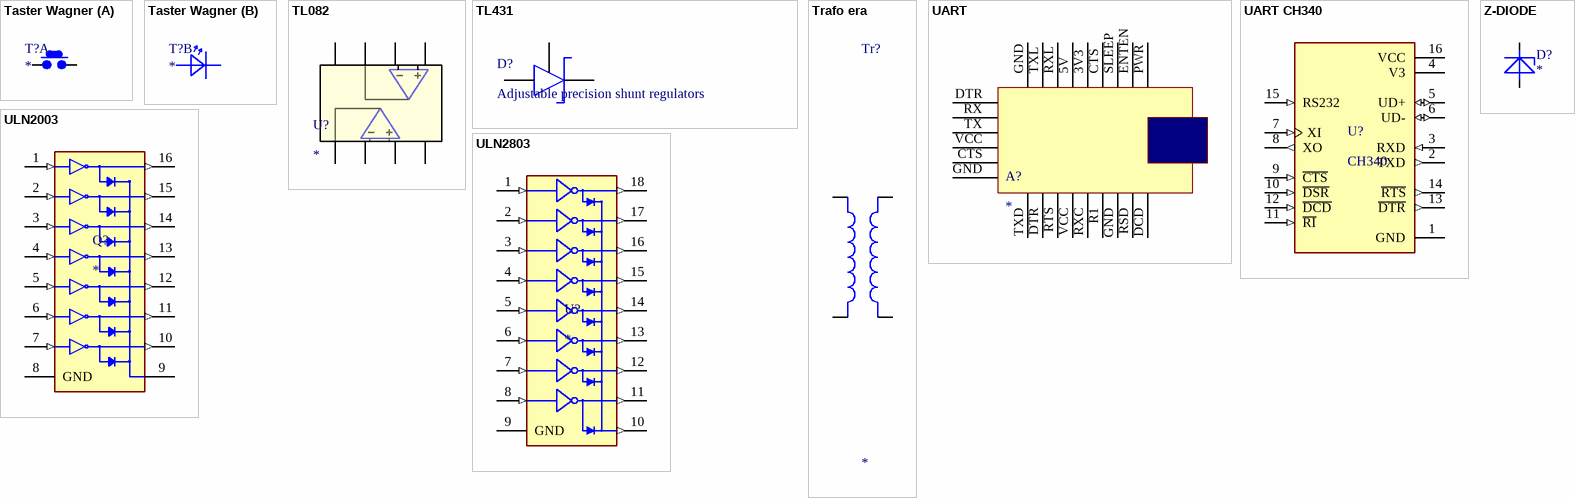
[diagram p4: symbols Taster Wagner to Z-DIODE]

## Taster Wagner
designator T?
Taster
footprint TasterWagner
part A pins: 1, 2
part B pins: 3 A, 4 K

## TL082
designator U?
OPV
footprint DIP-8
footprint SO-8
pins: 1, 2, 3, 4, 5, 6, 7, 8

## TL431
designator D?, comment Adjustable precision shunt regulators
Programmable Shunt Regulator Diode (NUR OHNE MFDT ENDE)
footprint SOT-23
footprint TO-92/3 DIO
pins: 1 Kathode, 2 REF, 3 Anode

## Trafo era
designator Tr?
Trafo; Text Field1: Sec1; Text Field2: Sec2; Text Field3: Sec3
footprint era trafo 6v
pins: 1 230V, 2 230V, 3 16V, 4 16V

## UART
designator A?
footprint uart
pins: 3V3 13, 5V 12, CTS 14, CTS 19, DCD 8, DTR 1, DTR 23, ENTEN 16, GND 6, GND 9, GND 18, PWR 17, R1 5, RSD 7, RTS 2, RX 22, RXC 4, RXL 11, SLEEP 15, TX 21, TXD 0, TXL 10, VCC 3, VCC 20

## UART CH340
designator U?, comment CH340
USB Interface Integrated Circuit; MP: Ch340G; MF: WCH
footprint SO-16
pins: 1 GND (power), 2 TXD (out), 3 RXD (in), 4 V3 (power), 5 UD+ (io), 6 UD- (io), 7 XI (in), 8 XO (out), 9 ~{CTS} (in), 10 ~{DSR} (in), 11 ~{RI} (in), 12 ~{DCD} (in), 13 ~{DTR} (out), 14 ~{RTS} (out), 15 RS232 (in), 16 VCC (power)

## ULN2003
designator Q?
Darlingtor-Transistor; MP: ULN2003AN
footprint DIP-16
footprint SO-16
pins: 1 1B (in), 2 2B (in), 3 3B (in), 4 4B (in), 5 5B (in), 6 6B (in), 7 7B (in), 8 GND (power), 9 COM, 10 7C (out), 11 6C (out), 12 5C (out), 13 4C (out), 14 3C (out), 15 2C (out), 16 1C (out)

## ULN2803
designator U?
Darlington-Transistor; MP: ULN2803A; MF: STMicroelectronics
footprint DIP-18
pins: 1 IN_1 (in), 2 IN_2 (in), 3 IN_3 (in), 4 IN_4 (in), 5 IN_5 (in), 6 IN_6 (in), 7 IN_7 (in), 8 IN_8 (in), 9 GND (power), 10 COMMON (out), 11 OUT_8 (out), 12 OUT_7 (out), 13 OUT_6 (out), 14 OUT_5 (out), 15 OUT_4 (out), 16 OUT_3 (out), 17 OUT_2 (out), 18 OUT_1 (out)

## Z-DIODE
designator D?
Z-Diode
footprint DIODE-0.4
footprint SOD-80
pins: 1 A, 2 K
